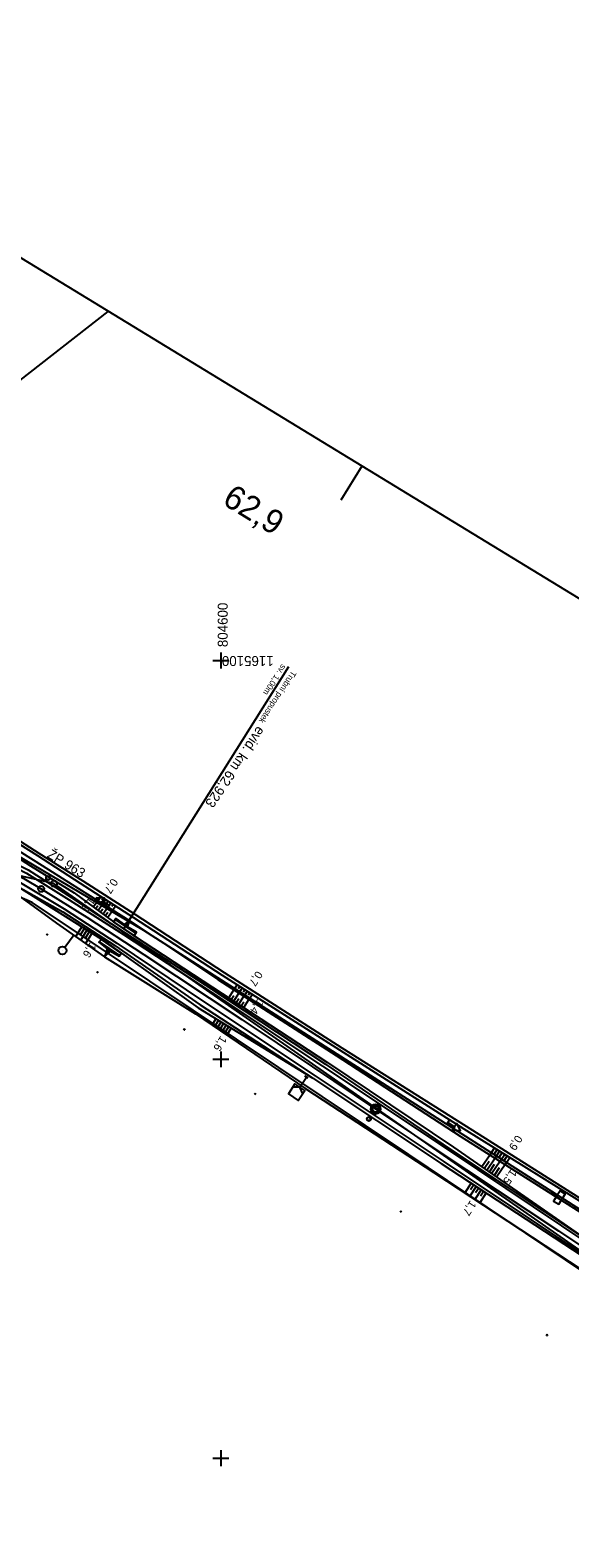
# Model space of a CAD drawing. Extents: x -804899 to -803847, y -1165742 to -1164942.
# Drawn here: x -804647.9 to -804512.4, y -1165320 to -1164941.9 of the extents above; entities that cross this region are included whole.
import ezdxf

# ---------------------------------------------------------------- set-up
doc = ezdxf.new("R2010")
doc.units = 0
for name, color, linetype in [('0381KM061-064P - Vrstva 1', 7, 'Continuous'), ('0381KM061-064P - Vrstva 17', 7, 'Continuous'), ('0381KM061-064P - Vrstva 19', 7, 'Continuous'), ('0381KM061-064P - Vrstva 36', 7, 'Continuous'), ('0381KM061-064P - Vrstva 4', 7, 'Continuous'), ('0381KM061-064P - Vrstva 48', 7, 'Continuous'), ('0381KM061-064P - Vrstva 49', 7, 'Continuous'), ('0381KM061-064P - Vrstva 51', 7, 'Continuous'), ('0381KM061-064P - Vrstva 55', 7, 'Continuous'), ('0381KM061-064P - Vrstva 7', 7, 'Continuous'), ('formát', 7, 'Continuous'), ('hran DP - hran DP', 7, 'Continuous'), ('krizky_1000 - souradnice', 7, 'Continuous'), ('krizky_1000 - Vrstva 1', 7, 'Continuous'), ('vyt_sit - polygon', 7, 'Continuous'), ('vyt_sit - stávající', 7, 'Continuous')]:
    doc.layers.add(name, color=color, linetype=linetype)

msp = doc.modelspace()

# ---------------------------------------------------------------- linework, layer by layer
at = {"layer": '0381KM061-064P - Vrstva 1'}
for points in [[(-804666.44, -1165145.5), (-804649.48, -1165154.65), (-804645.14, -1165157.27), (-804633.7, -1165164.38), (-804619.36, -1165173.74)], [(-804619.36, -1165173.74), (-804594.78, -1165190.05), (-804577, -1165201.91), (-804561.16, -1165212.47), (-804538.32, -1165227.67), (-804515.3, -1165243.02), (-804489.41, -1165260.27), (-804477.81, -1165268), (-804447.6, -1165288.14), (-804422.03, -1165305.2), (-804398.19, -1165321.09), (-804394.23, -1165323.73), (-804371.85, -1165338.65), (-804349.9, -1165353.29), (-804326.64, -1165368.8), (-804303.84, -1165384.01), (-804280.33, -1165399.7), (-804257.04, -1165415.23), (-804233.85, -1165430.69)]]:
    msp.add_lwpolyline(points, dxfattribs=at)
at = {"layer": '0381KM061-064P - Vrstva 17'}
for p, q in [((-804621.51, -1165168.31), (-804626.41, -1165164.99)), ((-804625.42, -1165173.99), (-804630.34, -1165170.65))]:
    msp.add_line(p, q, dxfattribs=at)
at = {"layer": '0381KM061-064P - Vrstva 19'}
msp.add_line((-804624.36, -1165167.24), (-804582.93, -1165101.49), dxfattribs=at)
for points in [[(-804626.92, -1165165.53), (-804626.96, -1165165.56), (-804626.42, -1165164.7), (-804626.38, -1165164.82)], [(-804621.79, -1165169), (-804626.96, -1165165.56)], [(-804621.8, -1165168.94), (-804626.92, -1165165.53), (-804626.38, -1165164.82), (-804621.37, -1165168.24), (-804621.8, -1165168.94)], [(-804626.42, -1165164.7), (-804624.29, -1165166.16)], [(-804621.2, -1165168.14), (-804623.43, -1165166.8)], [(-804630, -1165169.94), (-804629.95, -1165169.87), (-804630.64, -1165170.63), (-804630.54, -1165170.53)], [(-804630.64, -1165170.63), (-804628.58, -1165172.3)], [(-804630, -1165169.94), (-804630.54, -1165170.53), (-804625.53, -1165174.1), (-804625.05, -1165173.39), (-804630, -1165169.94)], [(-804629.95, -1165169.87), (-804624.97, -1165173.36)], [(-804621.8, -1165168.94), (-804621.79, -1165169), (-804621.2, -1165168.14), (-804621.37, -1165168.24)], [(-804625.53, -1165174.17), (-804627.74, -1165172.9)], [(-804625.05, -1165173.39), (-804624.97, -1165173.36), (-804625.53, -1165174.17), (-804625.53, -1165174.1)]]:
    msp.add_lwpolyline(points, dxfattribs=at)
for centre, major_axis, ratio, start_param, end_param in [((-804623.85, -1165166.5), (0.523, -0.388), 0.037903, 2.58802, 6.935719), ((-804623.82, -1165166.48), (-0.635, 0.468), 0.043076, 0.77347, 2.26914), ((-804628.16, -1165172.59), (-0.458, 0.324), 0.038427, 2.752706, 6.687548), ((-804628.11, -1165172.52), (0.511, -0.363), 0.262854, 3.749744, 5.691062)]:
    msp.add_ellipse(centre, major_axis=major_axis, ratio=ratio, start_param=start_param, end_param=end_param, dxfattribs=at)
at = {"layer": '0381KM061-064P - Vrstva 36'}
for p, q in [((-804639.21, -1165171.9), (-804636.83, -1165168.69)), ((-804639.81, -1165172.7), (-804639.81, -1165172.7))]:
    msp.add_line(p, q, dxfattribs=at)
msp.add_circle((-804639.81, -1165172.7), 1, dxfattribs=at)
at = {"layer": '0381KM061-064P - Vrstva 4'}
for points in [[(-804760.26, -1165118.8), (-804748.36, -1165120.01), (-804721.79, -1165126), (-804699.13, -1165133.38), (-804682.38, -1165139.58), (-804672.62, -1165144.09), (-804650.43, -1165155.7), (-804639.38, -1165162.29), (-804626.13, -1165170.89), (-804604.37, -1165185.52), (-804576.36, -1165204.15)], [(-804760.26, -1165118.8), (-804748.39, -1165120.75), (-804721.77, -1165126.98), (-804699.38, -1165134.38), (-804682.72, -1165140.57), (-804673.68, -1165144.67), (-804650.96, -1165156.64), (-804639.65, -1165163.02), (-804626.64, -1165171.43)], [(-804755.73, -1165115.93), (-804748.17, -1165116.91), (-804721.25, -1165123.25), (-804698.66, -1165130.22), (-804681.33, -1165136.99), (-804671.47, -1165141.65), (-804648.84, -1165153.36), (-804638.11, -1165160.03), (-804624.48, -1165168.7), (-804602.56, -1165183.07), (-804574.47, -1165201.72), (-804542.72, -1165222.84), (-804507.36, -1165246.55), (-804477.08, -1165266.82), (-804448.75, -1165285.88), (-804421.18, -1165304.15), (-804392.89, -1165323.09), (-804369.85, -1165338.37), (-804348.86, -1165352.04), (-804325.13, -1165367.98), (-804299.32, -1165385.27), (-804266.05, -1165407.31), (-804234.28, -1165428.6)], [(-804755.73, -1165115.93), (-804748.03, -1165116.49), (-804721.05, -1165122.36), (-804698.44, -1165129.77), (-804680.98, -1165136.5), (-804671.21, -1165140.89), (-804648.42, -1165152.46), (-804637.55, -1165159.43), (-804624.04, -1165168.29), (-804602.25, -1165182.38), (-804573.74, -1165201.2), (-804542.46, -1165222.56), (-804507.06, -1165246.03), (-804476.47, -1165266.24), (-804448.31, -1165285.08), (-804421.02, -1165303.1), (-804392.59, -1165322.59), (-804369.41, -1165337.65), (-804348.68, -1165351.59), (-804324.76, -1165367.42), (-804298.9, -1165384.42), (-804265.65, -1165406.5), (-804234.05, -1165428.04)], [(-804626.64, -1165171.43), (-804605.18, -1165186.34), (-804576.91, -1165204.69), (-804544.69, -1165226.09), (-804509.35, -1165249.3), (-804478.87, -1165269.77), (-804450.06, -1165288.98), (-804422.82, -1165307.11), (-804394.42, -1165325.66), (-804371.77, -1165341.24), (-804350.46, -1165355.38), (-804326.73, -1165371.34), (-804301.47, -1165388.34), (-804268.3, -1165410.72), (-804235.74, -1165432.01)], [(-804576.36, -1165204.15), (-804544.19, -1165225.52), (-804508.95, -1165249), (-804478.52, -1165269.18), (-804449.67, -1165288.56), (-804422.62, -1165306.58), (-804394.22, -1165325.33), (-804371.37, -1165340.61), (-804350.54, -1165354.66), (-804326.31, -1165370.81), (-804300.9, -1165387.72), (-804267.8, -1165409.92), (-804235.52, -1165431.44)]]:
    msp.add_lwpolyline(points, dxfattribs=at)
at = {"layer": '0381KM061-064P - Vrstva 48'}
for p, q in [((-804632.09, -1165161.79), (-804630.93, -1165160.22)), ((-804630.19, -1165159.11), (-804630.91, -1165160.23)), ((-804629.56, -1165159.52), (-804629.91, -1165160.07)), ((-804628.93, -1165159.92), (-804629.64, -1165161.03)), ((-804628.3, -1165160.33), (-804628.65, -1165160.88)), ((-804631.49, -1165162.24), (-804630.89, -1165161.43)), ((-804630.88, -1165162.68), (-804629.66, -1165161.02)), ((-804630.28, -1165163.12), (-804629.65, -1165162.27)), ((-804629.68, -1165163.57), (-804628.39, -1165161.82)), ((-804629.07, -1165164.01), (-804628.41, -1165163.12)), ((-804628.47, -1165164.46), (-804627.11, -1165162.62)), ((-804627.66, -1165160.74), (-804628.37, -1165161.83)), ((-804627.03, -1165161.14), (-804627.38, -1165161.69)), ((-804626.4, -1165161.55), (-804627.1, -1165162.63)), ((-804636.42, -1165169.21), (-804634.88, -1165166.77)), ((-804635.19, -1165170.08), (-804633.61, -1165167.56)), ((-804635.18, -1165168.65), (-804634.24, -1165167.17)), ((-804633.93, -1165169.49), (-804632.97, -1165167.97)), ((-804633.96, -1165170.94), (-804632.34, -1165168.36)), ((-804598.06, -1165184.55), (-804596.75, -1165182.56)), ((-804595.91, -1165181.26), (-804596.74, -1165182.56)), ((-804595.28, -1165181.67), (-804595.69, -1165182.32)), ((-804594.65, -1165182.07), (-804595.48, -1165183.37)), ((-804594.01, -1165182.47), (-804594.43, -1165183.13)), ((-804593.38, -1165182.88), (-804594.21, -1165184.19)), ((-804597.43, -1165184.97), (-804596.77, -1165183.97)), ((-804596.8, -1165185.38), (-804595.48, -1165183.37)), ((-804596.18, -1165185.79), (-804595.51, -1165184.78)), ((-804595.55, -1165186.2), (-804594.22, -1165184.18)), ((-804594.92, -1165186.61), (-804594.26, -1165185.6)), ((-804594.29, -1165187.02), (-804592.96, -1165184.99)), ((-804592.75, -1165183.28), (-804593.17, -1165183.94)), ((-804592.12, -1165183.68), (-804592.95, -1165185)), ((-804602.21, -1165191.42), (-804601.25, -1165189.83)), ((-804601.2, -1165191.2), (-804600.61, -1165190.23)), ((-804600.97, -1165192.26), (-804599.97, -1165190.62)), ((-804599.94, -1165192.01), (-804599.33, -1165191.01)), ((-804599.73, -1165193.11), (-804598.69, -1165191.4)), ((-804598.68, -1165192.83), (-804598.05, -1165191.79)), ((-804598.49, -1165193.95), (-804597.41, -1165192.18)), ((-804532.42, -1165223.96), (-804534.52, -1165226.99)), ((-804532.42, -1165223.97), (-804531.32, -1165222.2)), ((-804531.34, -1165223.66), (-804530.68, -1165222.6)), ((-804531.15, -1165224.77), (-804530.05, -1165223)), ((-804530.07, -1165224.46), (-804529.41, -1165223.39)), ((-804529.88, -1165225.57), (-804528.77, -1165223.79)), ((-804528.8, -1165225.26), (-804528.14, -1165224.18)), ((-804528.61, -1165226.37), (-804527.5, -1165224.58)), ((-804532.63, -1165225.59), (-804533.9, -1165227.42)), ((-804531.15, -1165224.77), (-804533.29, -1165227.85)), ((-804531.38, -1165226.41), (-804532.67, -1165228.27)), ((-804529.88, -1165225.57), (-804532.06, -1165228.7)), ((-804530.12, -1165227.23), (-804531.44, -1165229.13)), ((-804528.61, -1165226.37), (-804530.82, -1165229.55)), ((-804537.15, -1165231.04), (-804538.77, -1165233.51)), ((-804535.89, -1165231.86), (-804537.51, -1165234.33)), ((-804536.52, -1165231.45), (-804537.33, -1165232.69)), ((-804535.27, -1165232.28), (-804536.08, -1165233.51)), ((-804534.64, -1165232.69), (-804536.26, -1165235.15)), ((-804533.39, -1165233.51), (-804535.01, -1165235.98)), ((-804534.01, -1165233.1), (-804534.82, -1165234.33))]:
    msp.add_line(p, q, dxfattribs=at)
at = {"layer": '0381KM061-064P - Vrstva 49'}
for p, q in [((-804624.29, -1165166.16), (-804622.88, -1165165.28)), ((-804623.76, -1165166.56), (-804622.88, -1165165.28)), ((-804623.43, -1165166.8), (-804622.88, -1165165.28)), ((-804643.42, -1165168.96), (-804643.77, -1165168.6)), ((-804643.42, -1165168.6), (-804643.77, -1165168.96)), ((-804628.13, -1165172.71), (-804629.21, -1165174.28)), ((-804630.84, -1165178.37), (-804631.19, -1165178.02)), ((-804630.84, -1165178.02), (-804631.19, -1165178.37)), ((-804609.02, -1165192.71), (-804609.37, -1165192.36)), ((-804609.02, -1165192.36), (-804609.37, -1165192.71)), ((-804591.22, -1165208.93), (-804591.58, -1165208.57)), ((-804591.22, -1165208.57), (-804591.58, -1165208.93)), ((-804554.65, -1165238.41), (-804555.01, -1165238.06)), ((-804554.65, -1165238.06), (-804555.01, -1165238.41)), ((-804517.98, -1165269.33), (-804518.34, -1165268.98)), ((-804517.98, -1165268.98), (-804518.34, -1165269.33))]:
    msp.add_line(p, q, dxfattribs=at)
for points in [[(-804669.51, -1165137.6), (-804647.83, -1165151.5), (-804636.87, -1165158.28), (-804626.96, -1165165.56)], [(-804668.53, -1165136.56), (-804646.51, -1165150.38), (-804635.75, -1165157.19), (-804622.88, -1165165.28), (-804600.74, -1165180), (-804571.06, -1165199.05), (-804539.91, -1165219.23), (-804504.85, -1165241.38), (-804474.07, -1165260.59), (-804445.75, -1165278.86), (-804417.38, -1165297.08), (-804386.13, -1165316.29), (-804343.68, -1165343.22), (-804323.05, -1165356.81), (-804293.41, -1165375.48), (-804263.45, -1165394.43), (-804234.68, -1165412.78)], [(-804668.09, -1165135.13), (-804646.08, -1165148.91), (-804635.34, -1165155.79), (-804621.98, -1165164.4), (-804599.68, -1165178.86), (-804570.23, -1165197.63), (-804539.04, -1165217.4), (-804503.79, -1165239.32), (-804473.21, -1165259.25), (-804445.02, -1165277.37), (-804416.3, -1165295.6), (-804385.23, -1165314.87), (-804342.84, -1165342.16), (-804322.16, -1165355.5), (-804292.15, -1165374.6), (-804262.58, -1165393.44), (-804234.25, -1165411.43)], [(-804650.96, -1165156.64), (-804629.95, -1165169.87)], [(-804651.73, -1165158.22), (-804641.24, -1165165.82), (-804629.21, -1165174.28), (-804606.38, -1165188.59), (-804578.69, -1165207.38), (-804546.55, -1165228.41), (-804509.4, -1165252.77), (-804482.02, -1165272.35), (-804454.07, -1165289.87), (-804424.02, -1165310.32)], [(-804624.29, -1165166.16), (-804626.42, -1165164.7), (-804626.96, -1165165.56)], [(-804621.79, -1165169), (-804621.2, -1165168.14), (-804623.43, -1165166.8)], [(-804629.95, -1165169.87), (-804630.64, -1165170.63), (-804628.58, -1165172.3)], [(-804621.79, -1165169), (-804602.1, -1165181.9), (-804573.29, -1165200.8), (-804541.65, -1165222.05), (-804507.06, -1165246.03), (-804476.55, -1165265.48), (-804448.31, -1165285.08)], [(-804628.58, -1165172.3), (-804629.21, -1165174.28), (-804627.74, -1165172.9)], [(-804627.74, -1165172.9), (-804625.53, -1165174.17), (-804624.97, -1165173.36)], [(-804624.97, -1165173.36), (-804605.7, -1165187.12), (-804576.91, -1165204.69)], [(-804576.91, -1165204.69), (-804544.69, -1165226.09), (-804509.35, -1165249.3), (-804478.87, -1165269.77), (-804450.06, -1165288.98), (-804422.82, -1165307.11), (-804394.42, -1165325.66), (-804371.77, -1165341.24), (-804350.46, -1165355.38), (-804326.73, -1165371.34), (-804301.47, -1165388.34), (-804268.3, -1165410.72), (-804235.74, -1165432.01)]]:
    msp.add_lwpolyline(points, dxfattribs=at)
for centre, major_axis, ratio, start_param, end_param in [((-804623.82, -1165166.48), (0.635, -0.468), 0.043076, 3.915063, 5.410733), ((-804628.11, -1165172.52), (-0.511, 0.363), 0.262854, 0.608151, 2.549469)]:
    msp.add_ellipse(centre, major_axis=major_axis, ratio=ratio, start_param=start_param, end_param=end_param, dxfattribs=at)
at = {"layer": '0381KM061-064P - Vrstva 51'}
for p, q in [((-804628.33, -1165161.87), (-804627.81, -1165161.01)), ((-804542.75, -1165215.4), (-804543.3, -1165216.24)), ((-804516.68, -1165233.05), (-804517.22, -1165233.9))]:
    msp.add_line(p, q, dxfattribs=at)
for points in [[(-804728.9, -1165105.9), (-804711.54, -1165108.67), (-804704.35, -1165111.8), (-804683.69, -1165124.09), (-804676.95, -1165128.43), (-804667.36, -1165134.41), (-804645.71, -1165148.3), (-804634.7, -1165155.23), (-804621.63, -1165163.62), (-804599.19, -1165178.23), (-804569.67, -1165197.16), (-804538.42, -1165216.77), (-804503.41, -1165238.94), (-804472.82, -1165258.55), (-804444.57, -1165276.4), (-804415.82, -1165294.73), (-804384.7, -1165314.57), (-804342.59, -1165341.72), (-804321.8, -1165355.02), (-804291.77, -1165374.22), (-804262.45, -1165392.96)], [(-804628.07, -1165161.44), (-804629.78, -1165160.4), (-804629.26, -1165159.55), (-804631.28, -1165159.49), (-804630.3, -1165161.26), (-804629.78, -1165160.4)], [(-804543.03, -1165215.82), (-804541.36, -1165216.93), (-804541.91, -1165217.76), (-804539.9, -1165217.89), (-804540.81, -1165216.09), (-804541.36, -1165216.93)], [(-804516.95, -1165233.47), (-804515.68, -1165234.27), (-804516.48, -1165235.54), (-804515.21, -1165236.34), (-804513.61, -1165233.8), (-804514.88, -1165233), (-804515.68, -1165234.27)]]:
    msp.add_lwpolyline(points, dxfattribs=at)
at = {"layer": '0381KM061-064P - Vrstva 55'}
msp.add_lwpolyline([(-804834.02, -1165173.21), (-804777.95, -1165165.95), (-804761.65, -1165133.49), (-804755.48, -1165121.19), (-804751.26, -1165114.04), (-804741.92, -1165100.8), (-804736.13, -1165096.49), (-804701.79, -1165069.72), (-804628.3, -1165012.44)], dxfattribs=at)
at = {"layer": '0381KM061-064P - Vrstva 7'}
for p, q in [((-804643.44, -1165154.52), (-804643.36, -1165154.57)), ((-804580.17, -1165206.99), (-804578.52, -1165204.48)), ((-804578.1, -1165204.76), (-804578.93, -1165204.21)), ((-804562.9, -1165214.95), (-804562.82, -1165215.01))]:
    msp.add_line(p, q, dxfattribs=at)
for points in [[(-804580.17, -1165206.99), (-804581.42, -1165206.16), (-804583.08, -1165208.66), (-804580.58, -1165210.32), (-804578.92, -1165207.81), (-804580.17, -1165206.99)], [(-804579.47, -1165208.65), (-804580.17, -1165206.99), (-804581.98, -1165206.99)]]:
    msp.add_lwpolyline(points, dxfattribs=at)
for centre, radius in [((-804645.14, -1165157.27), 0.75), ((-804643.4, -1165154.55), 0.5), ((-804561.16, -1165212.47), 1.25), ((-804561.16, -1165212.47), 0.752), ((-804562.86, -1165214.98), 0.5)]:
    msp.add_circle(centre, radius, dxfattribs=at)
at = {"layer": 'formát'}
for p, q in [((-804206.05, -1165269.84), (-804743.98, -1164941.92)), ((-804564.67, -1165051.23), (-804569.87, -1165059.77))]:
    msp.add_line(p, q, dxfattribs=at)
at = {"layer": 'hran DP - hran DP'}
for p, q in [((-804647.39, -1165160.7), (-804728.07, -1165125.68)), ((-804680.02, -1165131.72), (-804619.47, -1165167.61)), ((-804628.74, -1165173.15), (-804647.39, -1165160.7)), ((-804619.47, -1165167.61), (-804573.03, -1165197.25)), ((-804552.85, -1165223.84), (-804628.74, -1165173.15)), ((-804573.03, -1165197.25), (-804519.76, -1165231.32)), ((-804418.46, -1165314.18), (-804552.85, -1165223.84)), ((-804519.76, -1165231.32), (-804468.27, -1165264.32))]:
    msp.add_line(p, q, dxfattribs=at)
at = {"layer": 'krizky_1000 - Vrstva 1'}
for points in [[(-804600, -1165098), (-804600, -1165102)], [(-804602, -1165100), (-804598, -1165100)], [(-804600, -1165198), (-804600, -1165202)], [(-804602, -1165200), (-804598, -1165200)], [(-804602, -1165300), (-804598, -1165300)], [(-804600, -1165298), (-804600, -1165302)]]:
    msp.add_lwpolyline(points, dxfattribs=at)
at = {"layer": 'vyt_sit - polygon'}
for p, q in [((-804641.93, -1165155.93), (-804836.52, -1165111.83)), ((-804442.66, -1165294.77), (-804641.93, -1165155.93))]:
    msp.add_line(p, q, dxfattribs=at)
at = {"layer": 'vyt_sit - stávající'}
msp.add_line((-804641.97, -1165155.91), (-804641.88, -1165155.96), dxfattribs=at)
msp.add_circle((-804641.93, -1165155.93), 0.756, dxfattribs=at)

# ---------------------------------------------------------------- texts
at = {"layer": '0381KM061-064P - Vrstva 19'}
for s, height, rotation, p in [('Trubní propustek', 1.5, 236.6035, (-804582.22, -1165102.45)), ('sv. 1,00m', 1.5, 236.6035, (-804584.72, -1165100.8)), ('evid. km 62,923', 2.5, 235.6365, (-804590.77, -1165116.28))]:
    msp.add_text(s, height=height, rotation=rotation, dxfattribs=at).set_placement(p)
at = {"layer": '0381KM061-064P - Vrstva 48'}
for s, rotation, p in [('0,7', 237.184, (-804627.36, -1165154.47)), ('1,2', 233.6713, (-804633.01, -1165159.16)), ('1,6', 237.8043, (-804632.81, -1165170.52)), ('0,7', 237.4892, (-804591.05, -1165177.68)), ('1,4', 236.7324, (-804590.78, -1165184.72)), ('1,6', 238.5896, (-804600.07, -1165193.98)), ('0,9', 238.1314, (-804525.86, -1165218.85)), ('1,5', 235.2728, (-804527.19, -1165227.42)), ('1,7', 236.7061, (-804537.39, -1165235.24))]:
    msp.add_text(s, height=2, rotation=rotation, dxfattribs=at).set_placement(p)
at = {"layer": '0381KM061-064P - Vrstva 7'}
msp.add_text('62,9', height=6, rotation=328.3791, dxfattribs=at).set_placement((-804599.94, -1165060.6))
at = {"layer": 'krizky_1000 - souradnice'}
for s, rotation, p in [('804600', 90, (-804598.3, -1165096.64)), ('1165100', 180, (-804586.75, -1165098.87))]:
    msp.add_text(s, height=2.5, rotation=rotation, dxfattribs=at).set_placement(p)
at = {"layer": 'vyt_sit - stávající'}
msp.add_text('ŽP 963', height=2.4, rotation=328.5611, dxfattribs=at).set_placement((-804643.81, -1165149.22))

doc.saveas('drawing.dxf')
